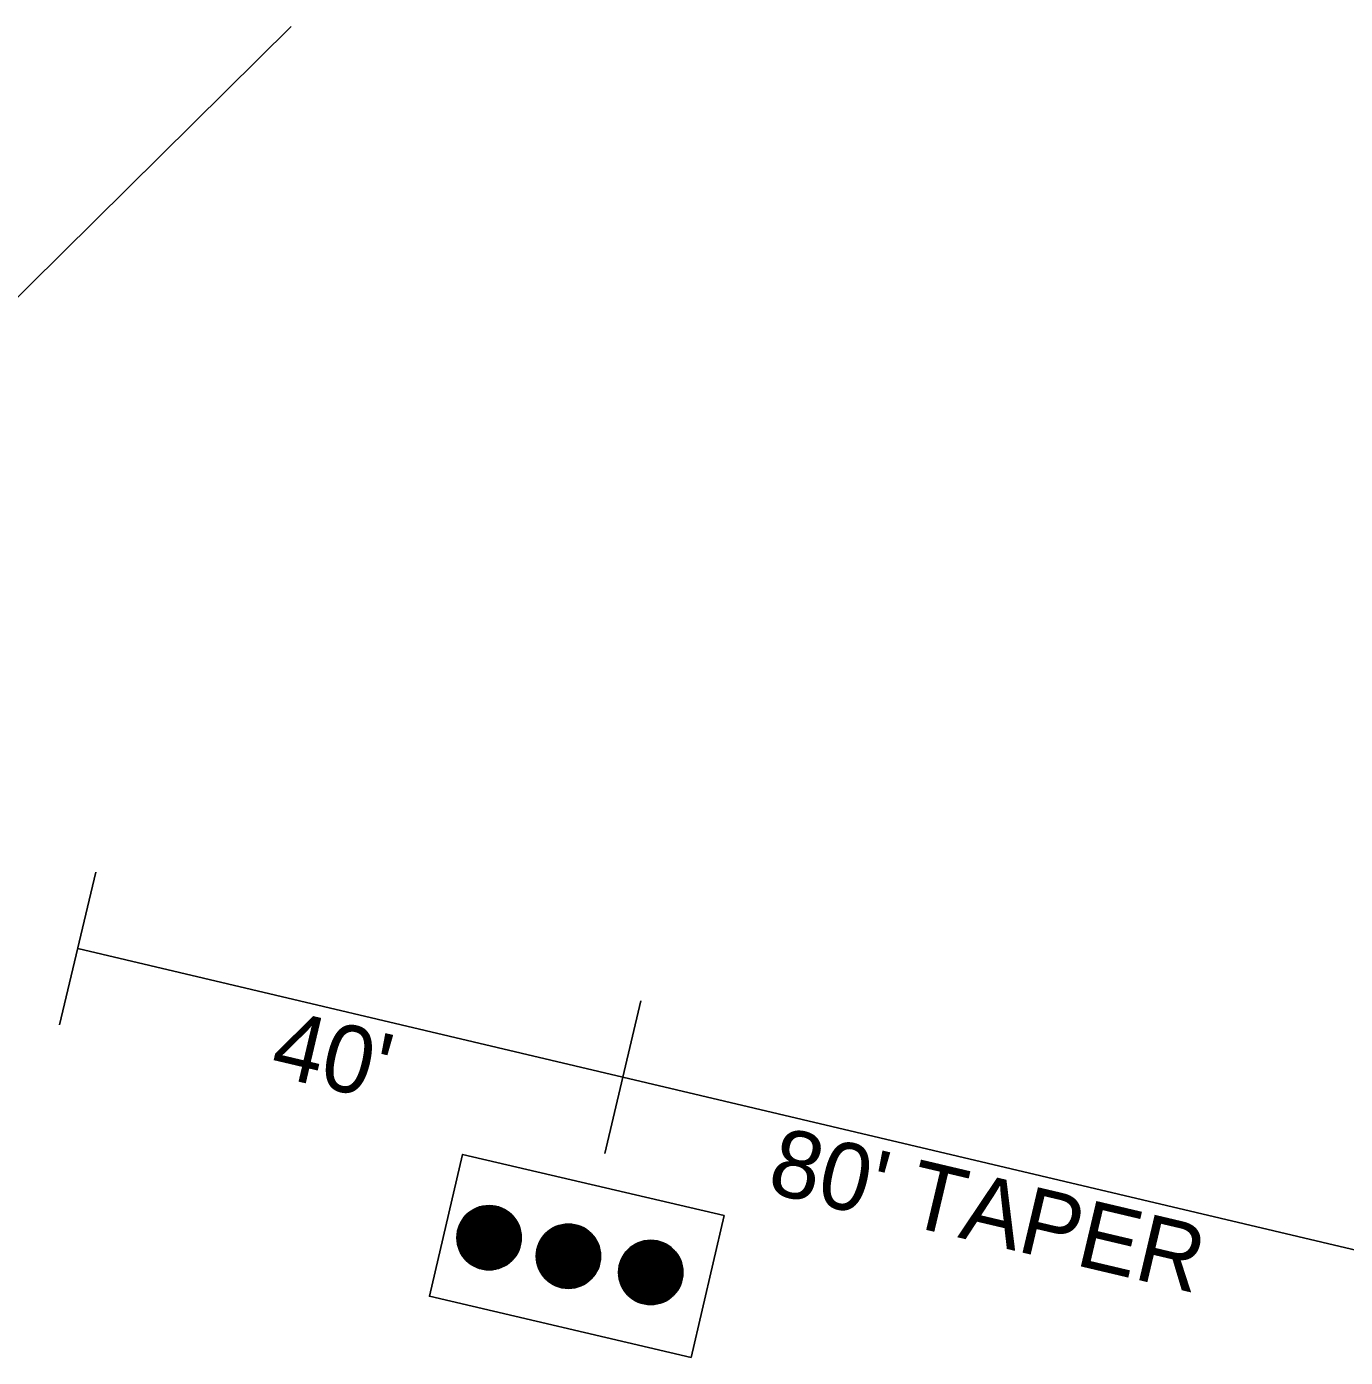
# Model space of a CAD drawing. Extents: x 1678017 to 1687792, y 404433 to 413488.
# Drawn here: x 1682187.6 to 1682305.3, y 407942.5 to 408061.3 of the extents above; entities that cross this region are included whole.
import ezdxf

# ---------------------------------------------------------------- set-up
doc = ezdxf.new("R2010")
doc.units = 0
doc.layers.add('Default', color=7, linetype='Continuous')

msp = doc.modelspace()

# ---------------------------------------------------------------- linework, layer by layer
at = {"layer": 'Default'}
for p, q in [((1682211.23, 408061.3), (1682105.83, 407957.07)), ((1682193.78, 407985.83), (1682190.56, 407972.2)), ((1682192.17, 407979.01), (1682240.84, 407967.52)), ((1682242.45, 407974.33), (1682239.23, 407960.71)), ((1682240.84, 407967.52), (1682317.93, 407949.31)), ((1682227.38, 407955.64), (1682230.41, 407950.75)), ((1682227.49, 407955.7), (1682230.52, 407950.82)), ((1682227.6, 407955.76), (1682230.62, 407950.9)), ((1682227.71, 407955.81), (1682230.72, 407950.97)), ((1682227.83, 407955.86), (1682230.81, 407951.06)), ((1682227.95, 407955.91), (1682230.91, 407951.14)), ((1682228.07, 407955.95), (1682231, 407951.24)), ((1682228.2, 407955.98), (1682231.08, 407951.33)), ((1682228.32, 407956.01), (1682231.17, 407951.44)), ((1682228.46, 407956.04), (1682231.25, 407951.54)), ((1682228.59, 407956.05), (1682231.32, 407951.66)), ((1682228.73, 407956.06), (1682231.39, 407951.78)), ((1682228.88, 407956.07), (1682231.46, 407951.91)), ((1682229.03, 407956.06), (1682231.52, 407952.04)), ((1682229.18, 407956.05), (1682231.58, 407952.19)), ((1682229.34, 407956.03), (1682231.64, 407952.34)), ((1682229.51, 407956), (1682231.68, 407952.5)), ((1682229.68, 407955.96), (1682231.72, 407952.68)), ((1682229.87, 407955.9), (1682231.75, 407952.87)), ((1682230.06, 407955.82), (1682231.76, 407953.08)), ((1682230.28, 407955.71), (1682231.76, 407953.32)), ((1682226.33, 407954.49), (1682228.92, 407950.32)), ((1682226.39, 407954.62), (1682229.06, 407950.32)), ((1682226.47, 407954.74), (1682229.2, 407950.34)), ((1682226.54, 407954.85), (1682229.34, 407950.35)), ((1682226.62, 407954.96), (1682229.47, 407950.38)), ((1682226.71, 407955.06), (1682229.6, 407950.41)), ((1682226.79, 407955.16), (1682229.72, 407950.44)), ((1682226.88, 407955.25), (1682229.85, 407950.48)), ((1682226.98, 407955.34), (1682229.96, 407950.53)), ((1682227.07, 407955.42), (1682230.08, 407950.58)), ((1682227.17, 407955.5), (1682230.19, 407950.63)), ((1682227.27, 407955.57), (1682230.3, 407950.69)), ((1682230.52, 407955.56), (1682231.74, 407953.6)), ((1682230.8, 407955.34), (1682231.66, 407953.95)), ((1682226.02, 407953.33), (1682227.74, 407950.56)), ((1682226.04, 407953.54), (1682227.93, 407950.48)), ((1682226.07, 407953.73), (1682228.12, 407950.42)), ((1682226.1, 407953.9), (1682228.29, 407950.38)), ((1682226.15, 407954.06), (1682228.46, 407950.35)), ((1682226.2, 407954.22), (1682228.61, 407950.33)), ((1682226.26, 407954.36), (1682228.77, 407950.32)), ((1682233.74, 407953.35), (1682236.61, 407948.73)), ((1682233.82, 407953.45), (1682236.73, 407948.77)), ((1682233.91, 407953.55), (1682236.86, 407948.8)), ((1682234, 407953.64), (1682236.98, 407948.85)), ((1682234.1, 407953.72), (1682237.1, 407948.89)), ((1682234.2, 407953.8), (1682237.21, 407948.94)), ((1682234.3, 407953.88), (1682237.32, 407949)), ((1682234.4, 407953.95), (1682237.43, 407949.06)), ((1682234.51, 407954.01), (1682237.54, 407949.13)), ((1682234.61, 407954.07), (1682237.64, 407949.2)), ((1682234.73, 407954.13), (1682237.74, 407949.27)), ((1682234.84, 407954.18), (1682237.84, 407949.35)), ((1682234.96, 407954.23), (1682237.93, 407949.44)), ((1682235.08, 407954.27), (1682238.03, 407949.53)), ((1682235.2, 407954.31), (1682238.11, 407949.62)), ((1682235.33, 407954.34), (1682238.2, 407949.72)), ((1682235.46, 407954.37), (1682238.28, 407949.83)), ((1682235.6, 407954.39), (1682238.36, 407949.94)), ((1682235.73, 407954.4), (1682238.43, 407950.06)), ((1682235.88, 407954.41), (1682238.5, 407950.18)), ((1682236.02, 407954.41), (1682238.57, 407950.31)), ((1682236.17, 407954.41), (1682238.63, 407950.45)), ((1682236.33, 407954.39), (1682238.69, 407950.6)), ((1682236.49, 407954.36), (1682238.74, 407950.75)), ((1682236.66, 407954.33), (1682238.78, 407950.92)), ((1682236.84, 407954.28), (1682238.81, 407951.11)), ((1682237.03, 407954.21), (1682238.83, 407951.31)), ((1682237.23, 407954.12), (1682238.84, 407951.53)), ((1682237.46, 407954), (1682238.83, 407951.78)), ((1682237.71, 407953.82), (1682238.79, 407952.09)), ((1682238.04, 407953.53), (1682238.67, 407952.51)), ((1682226.02, 407953.09), (1682227.53, 407950.66)), ((1682226.04, 407952.82), (1682227.29, 407950.8)), ((1682226.11, 407952.48), (1682227.01, 407951.02)), ((1682233.16, 407952.15), (1682235.27, 407948.75)), ((1682233.2, 407952.32), (1682235.44, 407948.71)), ((1682233.25, 407952.48), (1682235.61, 407948.69)), ((1682233.31, 407952.62), (1682235.76, 407948.67)), ((1682233.37, 407952.76), (1682235.91, 407948.66)), ((1682233.43, 407952.89), (1682236.06, 407948.66)), ((1682233.5, 407953.02), (1682236.2, 407948.67)), ((1682233.58, 407953.13), (1682236.34, 407948.69)), ((1682233.66, 407953.25), (1682236.47, 407948.71)), ((1682241.26, 407952.1), (1682244.21, 407947.36)), ((1682241.35, 407952.19), (1682244.33, 407947.4)), ((1682241.45, 407952.27), (1682244.44, 407947.44)), ((1682241.54, 407952.35), (1682244.56, 407947.5)), ((1682241.64, 407952.43), (1682244.67, 407947.55)), ((1682241.75, 407952.5), (1682244.78, 407947.61)), ((1682241.85, 407952.56), (1682244.89, 407947.68)), ((1682241.96, 407952.63), (1682244.99, 407947.75)), ((1682242.07, 407952.68), (1682245.09, 407947.83)), ((1682242.19, 407952.73), (1682245.19, 407947.91)), ((1682242.31, 407952.78), (1682245.28, 407947.99)), ((1682242.43, 407952.82), (1682245.37, 407948.08)), ((1682242.55, 407952.86), (1682245.46, 407948.18)), ((1682242.68, 407952.89), (1682245.55, 407948.28)), ((1682242.81, 407952.92), (1682245.63, 407948.38)), ((1682242.94, 407952.94), (1682245.71, 407948.49)), ((1682243.08, 407952.95), (1682245.78, 407948.61)), ((1682243.22, 407952.96), (1682245.85, 407948.73)), ((1682243.37, 407952.96), (1682245.92, 407948.86)), ((1682243.52, 407952.96), (1682245.98, 407949)), ((1682243.68, 407952.94), (1682246.03, 407949.15)), ((1682243.84, 407952.92), (1682246.08, 407949.31)), ((1682244.01, 407952.88), (1682246.13, 407949.48)), ((1682244.19, 407952.83), (1682246.16, 407949.66)), ((1682244.38, 407952.76), (1682246.18, 407949.86)), ((1682244.58, 407952.67), (1682246.19, 407950.08)), ((1682244.81, 407952.55), (1682246.18, 407950.33)), ((1682245.06, 407952.38), (1682246.14, 407950.64)), ((1682245.39, 407952.08), (1682246.02, 407951.07)), ((1682226.35, 407951.84), (1682226.55, 407951.52)), ((1682233.09, 407951.55), (1682234.7, 407948.96)), ((1682233.1, 407951.77), (1682234.9, 407948.87)), ((1682233.1, 407951.29), (1682234.48, 407949.08)), ((1682233.13, 407951.97), (1682235.09, 407948.8)), ((1682233.15, 407950.99), (1682234.22, 407949.25)), ((1682240.6, 407951.03), (1682242.95, 407947.24)), ((1682240.66, 407951.18), (1682243.11, 407947.22)), ((1682240.72, 407951.31), (1682243.26, 407947.22)), ((1682240.78, 407951.45), (1682243.41, 407947.22)), ((1682240.85, 407951.57), (1682243.55, 407947.22)), ((1682240.93, 407951.69), (1682243.69, 407947.24)), ((1682241.01, 407951.8), (1682243.82, 407947.26)), ((1682241.09, 407951.9), (1682243.95, 407947.29)), ((1682241.17, 407952), (1682244.08, 407947.32)), ((1682233.27, 407950.56), (1682233.89, 407949.55)), ((1682240.44, 407950.1), (1682242.05, 407947.51)), ((1682240.45, 407950.32), (1682242.25, 407947.42)), ((1682240.45, 407949.84), (1682241.83, 407947.63)), ((1682240.47, 407950.52), (1682242.44, 407947.35)), ((1682240.51, 407950.7), (1682242.62, 407947.3)), ((1682240.55, 407950.87), (1682242.79, 407947.26)), ((1682240.5, 407949.54), (1682241.57, 407947.81)), ((1682240.61, 407949.11), (1682241.24, 407948.1))]:
    msp.add_line(p, q, dxfattribs=at)
msp.add_lwpolyline([(1682249.87, 407955.16), (1682246.92, 407942.51), (1682223.57, 407947.97), (1682226.53, 407960.62)], close=True, dxfattribs=at)
for centre in [(1682228.89, 407953.19), (1682235.97, 407951.54), (1682243.32, 407950.09)]:
    msp.add_circle(centre, 2.87, dxfattribs=at)

# ---------------------------------------------------------------- texts
for s, p in [("40'", (1682209.17, 407967.76)), ("80' TAPER", (1682253.54, 407957.28))]:
    msp.add_text(s, height=6, rotation=346.7126, dxfattribs=at).set_placement(p)

doc.saveas('drawing.dxf')
